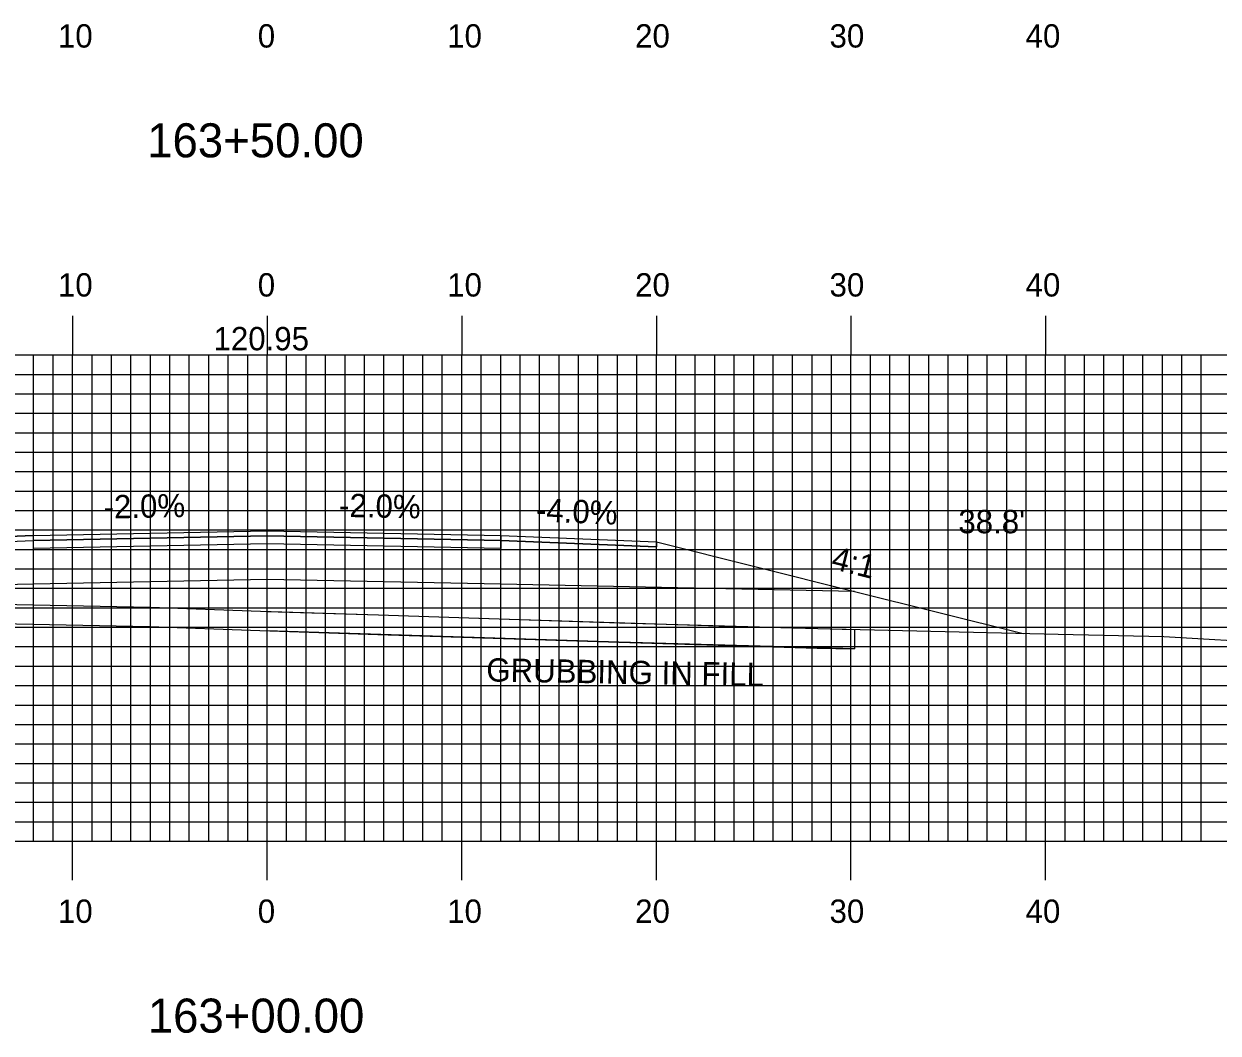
# Model space of a CAD drawing. Extents: x 1780680 to 1781023, y 442591 to 442811.
# Drawn here: x 1780832.9 to 1780894.2, y 442643.8 to 442695.7 of the extents above; entities that cross this region are included whole.
import ezdxf

# ---------------------------------------------------------------- set-up
doc = ezdxf.new("R2010")
doc.units = 0
for name, color, linetype in [('ANNOTATION', 7, 'Continuous'), ('D_Roadway_Centerline', 7, 'Continuous'), ('D_Roadway_Centerline_Text', 7, 'Continuous'), ('D_Roadway_Edge_Shoulder', 7, 'Continuous'), ('D_Roadway_Edge_TW', 7, 'Continuous'), ('D_Roadway_Pavement', 7, 'Continuous'), ('D_Roadway_SlopeLines', 7, 'Continuous'), ('D_Roadway_SubGrade', 7, 'Continuous'), ('D_Text_Standard', 7, 'Continuous'), ('GRUBBING IN FILL', 7, 'Continuous'), ('H_V ANNOTATION', 7, 'Continuous'), ('MAJOR', 7, 'Continuous'), ('MINOR', 7, 'Continuous'), ('S_Roadway_Centerline', 7, 'Continuous')]:
    doc.layers.add(name, color=color, linetype=linetype)

msp = doc.modelspace()

# ---------------------------------------------------------------- linework, layer by layer
at = {"layer": 'D_Roadway_Centerline'}
msp.add_lwpolyline([(1780804.594, 442666.234), (1780805.844, 442666.191), (1780807.094, 442666.1), (1780808.344, 442665.963), (1780809.594, 442665.778), (1780811.207, 442665.509), (1780815.207, 442666.509), (1780825.382, 442669.053), (1780833.382, 442669.373), (1780845.382, 442669.613), (1780857.382, 442669.373), (1780865.382, 442669.053), (1780875.556, 442666.509), (1780884.222, 442664.343)], dxfattribs=at)
at = {"layer": 'D_Roadway_Edge_Shoulder'}
for points in [[(1780833.382, 442669.373), (1780825.382, 442669.053), (1780825.382, 442668.803), (1780833.382, 442669.123)], [(1780857.382, 442669.373), (1780865.382, 442669.053), (1780865.382, 442668.803), (1780857.382, 442669.123)]]:
    msp.add_lwpolyline(points, close=True, dxfattribs=at)
at = {"layer": 'D_Roadway_Edge_TW'}
msp.add_lwpolyline([(1780833.382, 442669.123), (1780833.382, 442669.373), (1780845.382, 442669.613), (1780857.382, 442669.373), (1780857.382, 442669.123), (1780845.382, 442669.363)], close=True, dxfattribs=at)
at = {"layer": 'D_Roadway_Pavement'}
msp.add_lwpolyline([(1780833.382, 442668.706), (1780833.382, 442669.123), (1780845.382, 442669.363), (1780857.382, 442669.123), (1780857.382, 442668.706), (1780845.382, 442668.946)], close=True, dxfattribs=at)
at = {"layer": 'D_Roadway_SlopeLines'}
msp.add_lwpolyline([(1780865.382, 442669.053), (1780875.556, 442666.509), (1780884.222, 442664.343)], dxfattribs=at)
at = {"layer": 'D_Roadway_SubGrade'}
msp.add_lwpolyline([(1780833.382, 442666.873), (1780815.207, 442666.509), (1780825.382, 442669.053), (1780825.382, 442668.803), (1780833.382, 442669.123), (1780845.382, 442669.363), (1780857.382, 442669.123), (1780865.382, 442668.803), (1780865.382, 442669.053), (1780875.556, 442666.509), (1780857.382, 442666.873), (1780845.382, 442667.113)], close=True, dxfattribs=at)
at = {"layer": 'GRUBBING IN FILL'}
msp.add_line((1780875.556, 442664.551), (1780875.556, 442663.55), dxfattribs=at)
msp.add_line((1780875.556, 442664.551), (1780875.556, 442663.55), dxfattribs=at)
msp.add_lwpolyline([(1780815.213, 442665.083), (1780822.225, 442664.877), (1780828.207, 442664.917), (1780839.338, 442664.703), (1780845.003, 442664.492), (1780851.077, 442664.296), (1780863.458, 442663.893), (1780873.651, 442663.596), (1780875.556, 442663.55)], dxfattribs=at)
msp.add_lwpolyline([(1780815.213, 442665.083), (1780822.225, 442664.877), (1780828.207, 442664.917), (1780839.338, 442664.703), (1780845.003, 442664.492), (1780851.077, 442664.296), (1780863.458, 442663.893), (1780873.651, 442663.596), (1780875.556, 442663.55)], dxfattribs=at)
msp.add_lwpolyline([(1780875.556, 442664.551), (1780875.556, 442663.55), (1780863.458, 442663.893), (1780848.04, 442664.394), (1780845.382, 442664.48), (1780845.382, 442665.48), (1780851.11, 442665.295), (1780857.3, 442665.094), (1780868.584, 442664.744), (1780873.678, 442664.596)], close=True, dxfattribs=at)
msp.add_lwpolyline([(1780875.556, 442664.551), (1780875.556, 442663.55), (1780863.458, 442663.893), (1780848.04, 442664.394), (1780845.382, 442664.48), (1780845.382, 442665.48), (1780851.11, 442665.295), (1780857.3, 442665.094), (1780868.584, 442664.744), (1780873.678, 442664.596)], close=True, dxfattribs=at)
at = {"layer": 'MAJOR'}
for p, q in [((1780835.382, 442680.669), (1780835.382, 442678.665)), ((1780845.382, 442680.669), (1780845.382, 442678.665)), ((1780855.382, 442680.669), (1780855.382, 442678.665)), ((1780865.382, 442680.669), (1780865.382, 442678.665)), ((1780875.382, 442680.669), (1780875.382, 442678.665)), ((1780885.382, 442680.669), (1780885.382, 442678.665)), ((1780705.382, 442678.665), (1780985.382, 442678.665)), ((1780705.382, 442678.665), (1780985.382, 442678.665)), ((1780835.382, 442653.665), (1780835.382, 442678.665)), ((1780845.382, 442653.665), (1780845.382, 442678.665)), ((1780855.382, 442653.665), (1780855.382, 442678.665)), ((1780865.382, 442653.665), (1780865.382, 442678.665)), ((1780875.382, 442653.665), (1780875.382, 442678.665)), ((1780885.382, 442653.665), (1780885.382, 442678.665)), ((1780705.382, 442673.665), (1780985.382, 442673.665)), ((1780705.382, 442668.665), (1780985.382, 442668.665)), ((1780705.382, 442663.665), (1780985.382, 442663.665)), ((1780705.382, 442658.665), (1780985.382, 442658.665)), ((1780705.382, 442653.665), (1780985.382, 442653.665)), ((1780705.382, 442653.665), (1780985.382, 442653.665)), ((1780835.382, 442651.661), (1780835.382, 442653.665)), ((1780845.382, 442651.661), (1780845.382, 442653.665)), ((1780855.382, 442651.661), (1780855.382, 442653.665)), ((1780865.382, 442651.661), (1780865.382, 442653.665)), ((1780875.382, 442651.661), (1780875.382, 442653.665)), ((1780885.382, 442651.661), (1780885.382, 442653.665))]:
    msp.add_line(p, q, dxfattribs=at)
at = {"layer": 'MINOR'}
for p, q in [((1780833.382, 442653.665), (1780833.382, 442678.665)), ((1780834.382, 442653.665), (1780834.382, 442678.665)), ((1780836.382, 442653.665), (1780836.382, 442678.665)), ((1780837.382, 442653.665), (1780837.382, 442678.665)), ((1780838.382, 442653.665), (1780838.382, 442678.665)), ((1780839.382, 442653.665), (1780839.382, 442678.665)), ((1780840.382, 442653.665), (1780840.382, 442678.665)), ((1780841.382, 442653.665), (1780841.382, 442678.665)), ((1780842.382, 442653.665), (1780842.382, 442678.665)), ((1780843.382, 442653.665), (1780843.382, 442678.665)), ((1780844.382, 442653.665), (1780844.382, 442678.665)), ((1780846.382, 442653.665), (1780846.382, 442678.665)), ((1780847.382, 442653.665), (1780847.382, 442678.665)), ((1780848.382, 442653.665), (1780848.382, 442678.665)), ((1780849.382, 442653.665), (1780849.382, 442678.665)), ((1780850.382, 442653.665), (1780850.382, 442678.665)), ((1780851.382, 442653.665), (1780851.382, 442678.665)), ((1780852.382, 442653.665), (1780852.382, 442678.665)), ((1780853.382, 442653.665), (1780853.382, 442678.665)), ((1780854.382, 442653.665), (1780854.382, 442678.665)), ((1780856.382, 442653.665), (1780856.382, 442678.665)), ((1780857.382, 442653.665), (1780857.382, 442678.665)), ((1780858.382, 442653.665), (1780858.382, 442678.665)), ((1780859.382, 442653.665), (1780859.382, 442678.665)), ((1780860.382, 442653.665), (1780860.382, 442678.665)), ((1780861.382, 442653.665), (1780861.382, 442678.665)), ((1780862.382, 442653.665), (1780862.382, 442678.665)), ((1780863.382, 442653.665), (1780863.382, 442678.665)), ((1780864.382, 442653.665), (1780864.382, 442678.665)), ((1780866.382, 442653.665), (1780866.382, 442678.665)), ((1780867.382, 442653.665), (1780867.382, 442678.665)), ((1780868.382, 442653.665), (1780868.382, 442678.665)), ((1780869.382, 442653.665), (1780869.382, 442678.665)), ((1780870.382, 442653.665), (1780870.382, 442678.665)), ((1780871.382, 442653.665), (1780871.382, 442678.665)), ((1780872.382, 442653.665), (1780872.382, 442678.665)), ((1780873.382, 442653.665), (1780873.382, 442678.665)), ((1780874.382, 442653.665), (1780874.382, 442678.665)), ((1780876.382, 442653.665), (1780876.382, 442678.665)), ((1780877.382, 442653.665), (1780877.382, 442678.665)), ((1780878.382, 442653.665), (1780878.382, 442678.665)), ((1780879.382, 442653.665), (1780879.382, 442678.665)), ((1780880.382, 442653.665), (1780880.382, 442678.665)), ((1780881.382, 442653.665), (1780881.382, 442678.665)), ((1780882.382, 442653.665), (1780882.382, 442678.665)), ((1780883.382, 442653.665), (1780883.382, 442678.665)), ((1780884.382, 442653.665), (1780884.382, 442678.665)), ((1780886.382, 442653.665), (1780886.382, 442678.665)), ((1780887.382, 442653.665), (1780887.382, 442678.665)), ((1780888.382, 442653.665), (1780888.382, 442678.665)), ((1780889.382, 442653.665), (1780889.382, 442678.665)), ((1780890.382, 442653.665), (1780890.382, 442678.665)), ((1780891.382, 442653.665), (1780891.382, 442678.665)), ((1780892.382, 442653.665), (1780892.382, 442678.665)), ((1780893.382, 442653.665), (1780893.382, 442678.665)), ((1780705.382, 442677.665), (1780985.382, 442677.665)), ((1780705.382, 442676.665), (1780985.382, 442676.665)), ((1780705.382, 442675.665), (1780985.382, 442675.665)), ((1780705.382, 442674.665), (1780985.382, 442674.665)), ((1780705.382, 442672.665), (1780985.382, 442672.665)), ((1780705.382, 442671.665), (1780985.382, 442671.665)), ((1780705.382, 442670.665), (1780985.382, 442670.665)), ((1780705.382, 442669.665), (1780985.382, 442669.665)), ((1780705.382, 442667.665), (1780985.382, 442667.665)), ((1780705.382, 442666.665), (1780985.382, 442666.665)), ((1780705.382, 442665.665), (1780985.382, 442665.665)), ((1780705.382, 442664.665), (1780985.382, 442664.665)), ((1780705.382, 442662.665), (1780985.382, 442662.665)), ((1780705.382, 442661.665), (1780985.382, 442661.665)), ((1780705.382, 442660.665), (1780985.382, 442660.665)), ((1780705.382, 442659.665), (1780985.382, 442659.665)), ((1780705.382, 442657.665), (1780985.382, 442657.665)), ((1780705.382, 442656.665), (1780985.382, 442656.665)), ((1780705.382, 442655.665), (1780985.382, 442655.665)), ((1780705.382, 442654.665), (1780985.382, 442654.665))]:
    msp.add_line(p, q, dxfattribs=at)
at = {"layer": 'S_Roadway_Centerline'}
msp.add_lwpolyline([(1780784.173, 442666.779), (1780788.202, 442666.763), (1780791.742, 442666.497), (1780806.7, 442666.191), (1780810.539, 442666.226), (1780814.816, 442666.095), (1780822.236, 442665.877), (1780828.214, 442665.917), (1780839.367, 442665.703), (1780845.038, 442665.491), (1780851.11, 442665.295), (1780863.489, 442664.892), (1780873.678, 442664.596), (1780886.036, 442664.299), (1780891.457, 442664.184), (1780897.292, 442663.845)], dxfattribs=at)

# ---------------------------------------------------------------- texts
at = {"layer": 'ANNOTATION'}
for s, rotation, p in [('-2.0%', 1.14576, (1780836.988, 442670.245)), ('-2.0%', 358.85424, (1780849.068, 442670.339)), ('-4.0%', 357.70939, (1780859.173, 442670.103)), ('4:1', 345.96376, (1780874.308, 442667.683))]:
    msp.add_text(s, height=1.2, rotation=rotation, dxfattribs=at).set_placement(p)
at = {"layer": 'D_Roadway_Centerline'}
for s, p in [('C', (1780845.376, 442669.613)), ('L', (1780845.382, 442669.605))]:
    msp.add_text(s, height=0.0146, dxfattribs=at).set_placement(p)
at = {"layer": 'D_Roadway_Centerline_Text'}
msp.add_text('120.95', height=1.2, dxfattribs=at).set_placement((1780842.626, 442678.9))
at = {"layer": 'D_Text_Standard'}
msp.add_text("38.8'", height=1.2, dxfattribs=at).set_placement((1780880.898, 442669.495))
at = {"layer": 'GRUBBING IN FILL'}
msp.add_text('GRUBBING IN FILL', height=1.2, rotation=358.9728, dxfattribs=at).set_placement((1780856.634, 442661.879))
at = {"layer": 'H_V ANNOTATION'}
for s, height, p in [('10', 1.2, (1780834.632, 442694.465)), ('0', 1.2, (1780844.9, 442694.465)), ('10', 1.2, (1780854.632, 442694.465)), ('20', 1.2, (1780864.29, 442694.465)), ('30', 1.2, (1780874.279, 442694.465)), ('40', 1.2, (1780884.354, 442694.465)), ('163+50.00', 1.75, (1780839.217, 442688.821)), ('10', 1.2, (1780834.632, 442681.665)), ('0', 1.2, (1780844.9, 442681.665)), ('10', 1.2, (1780854.632, 442681.665)), ('20', 1.2, (1780864.29, 442681.665)), ('30', 1.2, (1780874.279, 442681.665)), ('40', 1.2, (1780884.354, 442681.665)), ('10', 1.2, (1780834.632, 442649.465)), ('0', 1.2, (1780844.9, 442649.465)), ('10', 1.2, (1780854.632, 442649.465)), ('20', 1.2, (1780864.29, 442649.465)), ('30', 1.2, (1780874.279, 442649.465)), ('40', 1.2, (1780884.354, 442649.465)), ('163+00.00', 1.75, (1780839.249, 442643.821))]:
    msp.add_text(s, height=height, dxfattribs=at).set_placement(p)

doc.saveas('drawing.dxf')
